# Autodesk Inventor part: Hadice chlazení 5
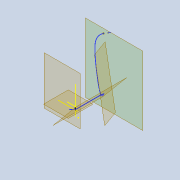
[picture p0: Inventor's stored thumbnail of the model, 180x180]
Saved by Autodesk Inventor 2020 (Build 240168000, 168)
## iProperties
Created: 2025-04
Part Number: Hadice chlazení 5
Material: Polyetylen, S nízkou hustotou
Document SubType Name: Modeling
Designer: doma
Density: 0.894 g/cm^3
Appearance: Modrá – nástěnná malba – lesklá
Author: doma
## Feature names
1. Tažení1
2. Vysunutí1 [Extrusion]
## Parameters: d2 = 5 mm, d4 = 55 deg, d6 = 130 deg, d9 = 113 deg, d14 = 90 deg, d20 = 85 deg, d21 = 185 mm, d25 = 5 mm, d29 = 8 mm, d30 = 0, d31 = 0, d32 = 5 mm, d33 = 84 mm, d35 = 0
